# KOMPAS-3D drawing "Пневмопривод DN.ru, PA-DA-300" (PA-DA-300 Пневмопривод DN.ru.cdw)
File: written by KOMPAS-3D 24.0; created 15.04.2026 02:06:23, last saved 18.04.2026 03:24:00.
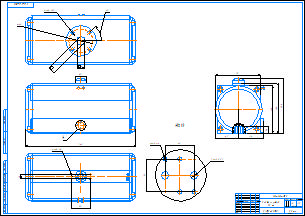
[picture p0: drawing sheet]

Document properties: Автор: DN.ru; Форматы листов документа: A1; Полное имя файла: PA-DA-300 Пневмопривод DN.ru.m3d; Масса: 110; Наименование: Пневмопривод DN.ru; Количество листов документа: 1; Примечание: D290-00302

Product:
- Part/product: Пневмопривод DN.ru  | designation PA-DA-300
    Масса: 110
    Раздел спецификации: Прочие изделия
    Примечание: D290-00302

Views: Вид 1, Вид:1, Проекционный вид 2, Проекционный вид 5, Местный разрез 1, Выносной элемент 6, Выносной элемент А, Выносной элемент
Referenced files in C:\Работа\PA-DA-х Пневмопривод DN.ru\052\: PA-DA-052 Пневмопривод DN.ru.m3d
Referenced files in C:\Работа\PA-DA-х Пневмопривод DN.ru\300\: PA-DA-300 Пневмопривод DN.ru.m3d
Referenced files in C:\Работа\PA-DA-х Пневмопривод DN.ru\160\: PA-DA-160 Пневмопривод DN.ru.m3d
Referenced files in C:\Program Files\ASCON\KOMPAS-3D v24\Templates\: Чертеж_DN.ru.cdt
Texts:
  objid
  viewid
  PA-DA-300
  Чертеж_DN.ru.cdt
  Пневмопривод
  Пневмопривод DN.ru
  PA-DA-300 Пневмопривод DN.ru
Dimensions and other numbers on the sheet: 0; 3; 2; 4; 80; 608; 760; 46; 165; 4 отв.; 20; 6; 312; 162; 174; 330; 350; 380; 50; 7; 1; 2 отв.; 40; 45; 1:2,5; 110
